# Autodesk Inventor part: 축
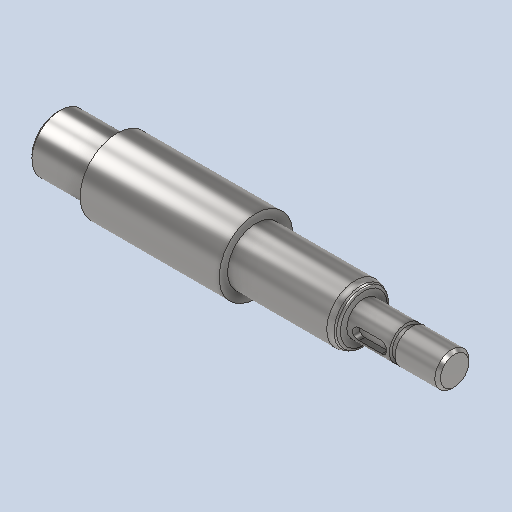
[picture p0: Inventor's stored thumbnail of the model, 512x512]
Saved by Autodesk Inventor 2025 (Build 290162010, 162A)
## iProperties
Created: 2024-08
Part Number: 축
Material: 강철, 연강
Document SubType Name: Modeling
Designer: 학생
Density: 7.86 g/cm^3
Appearance: 기본값
Author: jhkim
Sending System: Autodesk Inventor 2025
Preprocessor: ST-DEVELOPER v20
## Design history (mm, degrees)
feature "솔리드2"
node "솔리드1"
